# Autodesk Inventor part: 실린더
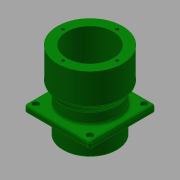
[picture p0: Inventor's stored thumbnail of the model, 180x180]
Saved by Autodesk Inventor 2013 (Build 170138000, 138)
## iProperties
Created: 2016-11
Part Number: 실린더
Material: 알루미늄 6061
Document SubType Name: Modeling
Designer: mduedu
Density: 2.71 g/cm^3
Mass: 551.099 g
Surface Area: 551.337 cm^2
Volume: 203.358 cm^3
Author: mduedu
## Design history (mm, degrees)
sketch "스케치1"
  geometry: L1 (0, 0)-(0, 101); L2 (30, 0)-(30, 101); L3 (30, 101)-(42, 101); L4 (42, 101)-(42, 61); L5 (42, 61)-(35, 51); L6 (35, 51)-(35, 0); L7 (35, 0)-(30, 0)
  constraints: 14 end point, 4 parallel, 2 horizontal alignment, 1 perpendicular, 1 vertical
  dimensions: "d0" = 101 distance of L1.start L1.end; "d1" = 60 diameter of L2.end L1; "d2" = 84 diameter of L3.end L1; "d3" = 70 diameter of L6.end L1; "d4" = 40 distance of L3.end L4.end; "d5" = 50 vertical distance of L5.end L3.end
revolve "회전1" sketch "스케치1" stored, may be unused: angle "d6" = 90 deg
node "작업 평면1"
sketch "스케치2"
  geometry: L1 (-42.5, -42.5)-(42.5, -42.5); L2 (42.5, -42.5)-(42.5, 42.5); L3 (42.5, 42.5)-(-42.5, 42.5); L4 (-42.5, 42.5)-(-42.5, -42.5); L5 (-42.5, -42.5)-(42.5, 42.5); L6 (42.5, -42.5)-(-42.5, 42.5); C1 r 35 at (0, 0) reference; C2 r 35 at (0, 0); 1 further point
  constraints: 12 end point, 2 midpoint, 2 parallel, 2 perpendicular, 1 centre point, 1 coincident, 1 concentric, 1 horizontal
  dimensions: "d8" = 85 distance of L2.end L3.end
extrude "돌출1" join sketch "스케치2" distance "d10" = 8; taper "d11" = 0 deg
fillet "모깎기1" dims "d12" = 3
fillet "모깎기2" dims "d13" = 3
chamfer "모따기1" distance "d14" = 1; stored, may be unused: second distance "d15" = 2, angle "d16" = 45 deg
chamfer "모따기2" distance "d17" = 5; stored, may be unused: second distance "d18" = 2, angle "d19" = 15 deg
sketch "스케치3"
  geometry: L1 (-35, -35)-(35, -35); L2 (35, -35)-(35, 35); L3 (35, 35)-(-35, 35); L4 (-35, 35)-(-35, -35); L5 (-35, -35)-(35, 35); L6 (35, -35)-(-35, 35); 5 further points
  constraints: 12 end point, 4 coincident, 2 midpoint, 2 parallel, 1 horizontal, 1 perpendicular
  dimensions: "d20" = 70 distance of L3.end L2.end; "d21" = 70 distance of L2.end L1.end
sketch "스케치4"
  geometry: 4 further points
  constraints: 4 other
hole "구멍1" sketch "스케치4" at (-35, 35), (35, 35), (35, -35), (-35, -35) diameter "d22" = 4.5; stored, may be unused: countersink angle "d26" = 90 deg, drill point angle "d28" = 0 deg; dims "d23" = 6, "d24" = 8, "d25" = 4.6, "d27" = 8
sketch "스케치5"
  geometry: 4 further points
  constraints: 4 other
hole "구멍2" sketch "스케치5" at (0, -35), (35, 0), (-35, 0), (0, 35) diameter "d29" = 4.134; stored, may be unused: countersink angle "d33" = 90 deg, drill point angle "d35" = 120 deg; dims "d30" = 7.5, "d31" = 4, "d32" = 2, "d34" = 10
node "솔리드1"
other parameters: "d7" = -27
